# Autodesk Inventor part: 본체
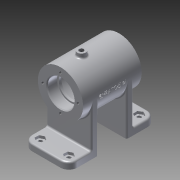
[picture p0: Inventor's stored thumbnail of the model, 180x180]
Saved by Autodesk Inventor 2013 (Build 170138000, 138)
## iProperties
Created: 2017-02
Part Number: 본체
Material: 알루미늄 6061
Document SubType Name: Modeling
Designer: Administrator
Density: 2.71 g/cm^3
Mass: 355.897 g
Surface Area: 423.344 cm^2
Volume: 131.327 cm^3
Author: Administrator
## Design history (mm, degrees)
sketch "스케치1"
  geometry: C1 r 27 at (0, 0); 1 further point
  constraints: 1 centre point, 1 coincident
  dimensions: "d0" = 54 diameter of C1
extrude "돌출1" new body sketch "스케치1" stored distance "d2" = 70; taper "d3" = 0 deg
node "작업 평면1"
sketch "스케치2"
  geometry: L1 (-27, 52)-(27, 52); L2 (27, 52)-(27, -52); L3 (27, -52)-(-27, -52); L4 (-27, -52)-(-27, 52); L5 (-27, 17)-(27, 17); L6 (27, 17)-(27, -17); L7 (27, -17)-(-27, -17); L8 (-27, -17)-(-27, 17); 2 further points
  constraints: 16 end point, 4 parallel, 2 horizontal, 2 perpendicular, 2 point on line, 1 coincident
  dimensions: "d5" = 104 distance of L1.end L2.end; "d7" = 54 distance of L1.start L1.end; "d8" = 52 vertical distance of point (0, 0) L1.end; "d13" = 17 vertical distance of L5.end point (0, 0); "d14" = 17 vertical distance of L6.end point (0, 0); "d15" = 27 horizontal distance of L1.start point (0, 0)
extrude "돌출3" join sketch "스케치2" distance "d16" = 8; taper "d17" = 0 deg
sketch "스케치4"
  geometry: L1 (-35, 27)-(-35, -27) reference; L2 (35, -27)-(35, 27) reference; L3 (-35, -27)-(-35, 27) reference; L4 (-35, 27)-(35, 27) reference; L5 (35, 27)-(35, -27) reference; L6 (35, -27)-(-35, -27) reference; L7 (-52, -60)-(-52, -52) reference; L8 (-52, -52)-(-17, -52) reference; L9 (-17, -52)-(-17, -60) reference; L10 (-17, -60)-(-52, -60) reference; L11 (17, -60)-(17, -52) reference; L12 (17, -52)-(52, -52) reference; L13 (52, -52)-(52, -60) reference; L14 (52, -60)-(17, -60) reference; L15 (-35, 0)-(-23, 0); L16 (-23, 0)-(-23, 15.7); L17 (-23.3, 16)-(-35, 16); L18 (-35, 16)-(-35, 0); L19 (-23, 0)-(-20, 0); L20 (-20, 0)-(-20, 14); L21 (-20, 14)-(-23, 14); L22 (-23, 14)-(-23, 0); L23 (-20, 0)-(20, 0); L24 (20, 0)-(20, 19); L25 (17, 22)-(-17, 22); L26 (-20, 19)-(-20, 0); L27 (20, 0)-(23, 0); L28 (23, 0)-(23, 14); L29 (23, 14)-(20, 14); L30 (20, 14)-(20, 0); L31 (23, 0)-(35, 0); L32 (35, 0)-(35, 16); L33 (35, 16)-(23.3, 16); L34 (23, 15.7)-(23, 0); A1 r 3 centre (-17, 19) between (-17, 22) and (-20, 19); A2 r 3 centre (17, 19) between (20, 19) and (17, 22); A3 r 0.3 centre (-23.3, 15.7) between (-23, 15.7) and (-23.3, 16); A4 r 0.3 centre (23.3, 15.7) between (23.3, 16) and (23, 15.7); 6 further points
  constraints: 40 end point, 10 parallel, 9 point on line, 8 point on circle, 8 tangent, 5 horizontal, 5 perpendicular, 4 centre point, 2 equal radius, 2 midpoint, 1 vertical alignment
  dimensions: "d18" = 32 diameter of L17 L15; "d20" = 28 diameter of L21 L19; "d21" = 44 diameter of L25 L23; "d22" = 28 diameter of L29 L27; "d23" = 32 diameter of L33 L31; "d24" = 12 distance of point (-23, 16) L17.end; "d25" = 40 distance between parallel lines of L24 L20; "d26" = 12 distance between parallel lines of L32 L28; "d28" = 3 radius of A1; "d29" = 0.3 radius of A3
revolve "회전1" sketch "스케치4" stored, may be unused: angle "d27" = 90 deg
chamfer "모따기1" distance "d30" = 1; stored, may be unused: second distance "d31" = 2, angle "d32" = 45 deg
chamfer "모따기2" distance "d33" = 1; stored, may be unused: second distance "d34" = 2, angle "d35" = 45 deg
sketch "스케치5"
  geometry: L1 (0, 0)-(0, 21); C1 r 17 at (0, 0) reference; 1 further point
  constraints: 2 end point, 1 coincident, 1 vertical
  dimensions: "d36" = 21 distance of L1.start L1.end
hole "구멍1" sketch "스케치5" at (0, 21) diameter "d37" = 3.242; stored, may be unused: countersink angle "d41" = 90 deg, drill point angle "d43" = 118 deg; dims "d38" = 8, "d39" = 4, "d40" = 2, "d42" = 10
node "작업 평면2"
sketch "스케치6"
  geometry: L1 (-27, -35)-(27, -35) reference; L2 (0, -35)-(0, -10); C1 r 5 at (0, -10); 1 further point
  constraints: 2 end point, 1 centre point, 1 coincident, 1 midpoint, 1 perpendicular
  dimensions: "d48" = 25 distance of L2.start L2.end; "d50" = 10 diameter of C1
extrude "돌출4" join sketch "스케치6" stored distance "d51" = 8; taper "d52" = 0 deg
sketch "스케치7"
  geometry: C1 r 5 at (0, 0) reference; 2 further points
  constraints: 1 coincident
hole "구멍2" sketch "스케치7" at (0, 0) diameter "d53" = 5.188; stored, may be unused: countersink angle "d57" = 90 deg, drill point angle "d59" = 118 deg; dims "d54" = 10, "d55" = 4, "d56" = 2, "d58" = 10
node "작업 평면3"
sketch "스케치8"
  geometry: L1 (0, 0)-(0, 50.474); L2 (0, 0)-(-16.339, 25.16)
  constraints: 4 end point, 1 vertical
  dimensions: "d61" = 33 deg angle of L1 L2; "d62" = 30 distance of L1.start L2.end
node "작업 평면4"
  node "작업점1"
sketch "스케치9"
  geometry: C1 r 6 at (0, 0); 1 further point
  constraints: 1 centre point, 1 coincident
  dimensions: "d63" = 12 diameter of C1
extrude "돌출5" join sketch "스케치9" stored distance "d65" = 8; taper "d66" = 0 deg
sketch "스케치10"
  geometry: C1 r 6 at (0, 0) reference; 1 further point
  constraints: 1 coincident
hole "구멍3" sketch "스케치10" at (0, 0) diameter "d67" = 5.188; stored, may be unused: countersink angle "d71" = 90 deg, drill point angle "d73" = 118 deg; dims "d68" = 8, "d69" = 4, "d70" = 2, "d72" = 10
sketch "스케치11"
  geometry: L1 (-27, 17)-(27, 17) reference; L2 (27, 17)-(27, 52) reference; L3 (-27, 17)-(27, 17); L4 (27, 17)-(27, 25); L5 (27, 25)-(-27, 25); L6 (-27, 25)-(-27, 17); L7 (-27, -17)-(27, -17) reference; L8 (27, -52)-(27, -17) reference; L9 (-27, -52)-(27, -52) reference; L10 (-27, -17)-(-27, -52) reference; L11 (-27, -17)-(27, -17); L12 (27, -17)-(27, -25); L13 (27, -25)-(-27, -25); L14 (-27, -25)-(-27, -17); 1 further point
  constraints: 16 end point, 4 parallel, 2 horizontal, 2 perpendicular, 2 point on line
  dimensions: "d74" = 8 distance of L3.end L4.end; "d76" = 8 distance of L11.end L12.end
extrude "돌출6" join sketch "스케치11" stored distance "d77" = 8; taper "d78" = 0 deg
fillet "모깎기1" dims "d79" = 10
sketch "스케치13"
  geometry: L1 (-17, -52)-(17, -52) reference; L2 (-27, -17)-(-27, -42) reference; L3 (-27, -17)-(27, -17) reference; L4 (27, -42)-(27, -17) reference; A1 r 10 centre (-17, 42) between (-17, 52) and (-27, 42) reference; A2 r 10 centre (17, 42) between (27, 42) and (17, 52) reference; A3 r 10 centre (17, -42) between (17, -52) and (27, -42) reference; A4 r 10 centre (-17, -42) between (-27, -42) and (-17, -52) reference; 5 further points
  constraints: 4 coincident
hole "구멍4" sketch "스케치13" at (-17, 42), (17, 42), (17, -42), (-17, -42) diameter "d80" = 5; stored, may be unused: countersink angle "d84" = 90 deg, drill point angle "d86" = 118 deg; dims "d81" = 8, "d82" = 9, "d83" = 3, "d85" = 10
sketch "스케치14"
  geometry: L1 (-12.339, -39.703)-(-12.681, -44.888); L2 (-12.681, -44.888)-(-17.342, -47.185); L3 (-17.342, -47.185)-(-21.661, -44.297); L4 (-21.661, -44.297)-(-21.319, -39.112); L5 (-21.319, -39.112)-(-16.658, -36.815); L6 (-16.658, -36.815)-(-12.339, -39.703); L7 (21.661, -39.703)-(21.319, -44.888); L8 (21.319, -44.888)-(16.658, -47.185); L9 (16.658, -47.185)-(12.339, -44.297); L10 (12.339, -44.297)-(12.681, -39.112); L11 (12.681, -39.112)-(17.342, -36.815); L12 (17.342, -36.815)-(21.661, -39.703); L13 (-12.339, 44.297)-(-12.681, 39.112); L14 (-12.681, 39.112)-(-17.342, 36.815); L15 (-17.342, 36.815)-(-21.661, 39.703); L16 (-21.661, 39.703)-(-21.319, 44.888); L17 (-21.319, 44.888)-(-16.658, 47.185); L18 (-16.658, 47.185)-(-12.339, 44.297); L19 (21.5, 44.888)-(21.751, 39.547); L20 (21.751, 39.547)-(17.251, 36.659); L21 (17.251, 36.659)-(12.5, 39.112); L22 (12.5, 39.112)-(12.249, 44.453); L23 (12.249, 44.453)-(16.749, 47.341); L24 (16.749, 47.341)-(21.5, 44.888); C1 r 4.5 at (17, 42) reference; A1 r 10 centre (17, -42) between (17, -52) and (27, -42) reference; 11 further points
  constraints: 48 end point, 4 coincident, 3 midpoint, 58 other
extrude "돌출7" cut sketch "스케치14" distance "d87" = 3; taper "d88" = 0 deg
node "작업 평면5"
sketch "스케치15"
  geometry: L1 (-35, 27)-(-35, -27) reference; L2 (-35, 27)-(35, 27) reference; L3 (-17.123, 2.191)-(17.123, 2.191); L4 (17.123, 2.191)-(17.123, -2.191); L5 (17.123, -2.191)-(-17.123, -2.191); L6 (-17.123, -2.191)-(-17.123, 2.191); L7 (0, 2.191)-(0, -2.191); L8 (-17.123, 0)-(17.123, 0); 2 further points
  constraints: 5 midpoint, 4 end point, 1 coincident, 2 other
feature "엠보싱1" sketch "스케치15" dims "d90" = 0.5, "d91" = 0
fillet "모깎기2" dims "d92" = 2
fillet "모깎기3" dims "d93" = 2
node "솔리드1"
pattern_circular "원형 패턴1" dims angle "d45" = 360 deg
mirror "대칭1"
node "투영된 루프1"
node "투영된 루프2"
node "투영된 루프3"
node "절단 모서리 투영1"
other parameters: "d47" = -92, "d60" = -35
